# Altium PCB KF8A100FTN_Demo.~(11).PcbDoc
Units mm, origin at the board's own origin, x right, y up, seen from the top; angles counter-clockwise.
Board outline 152.4 x 101.6 mm, 2 copper layers (Top Layer, Bottom Layer); 25 components, 0 nets, 113 pads, 0 vias.
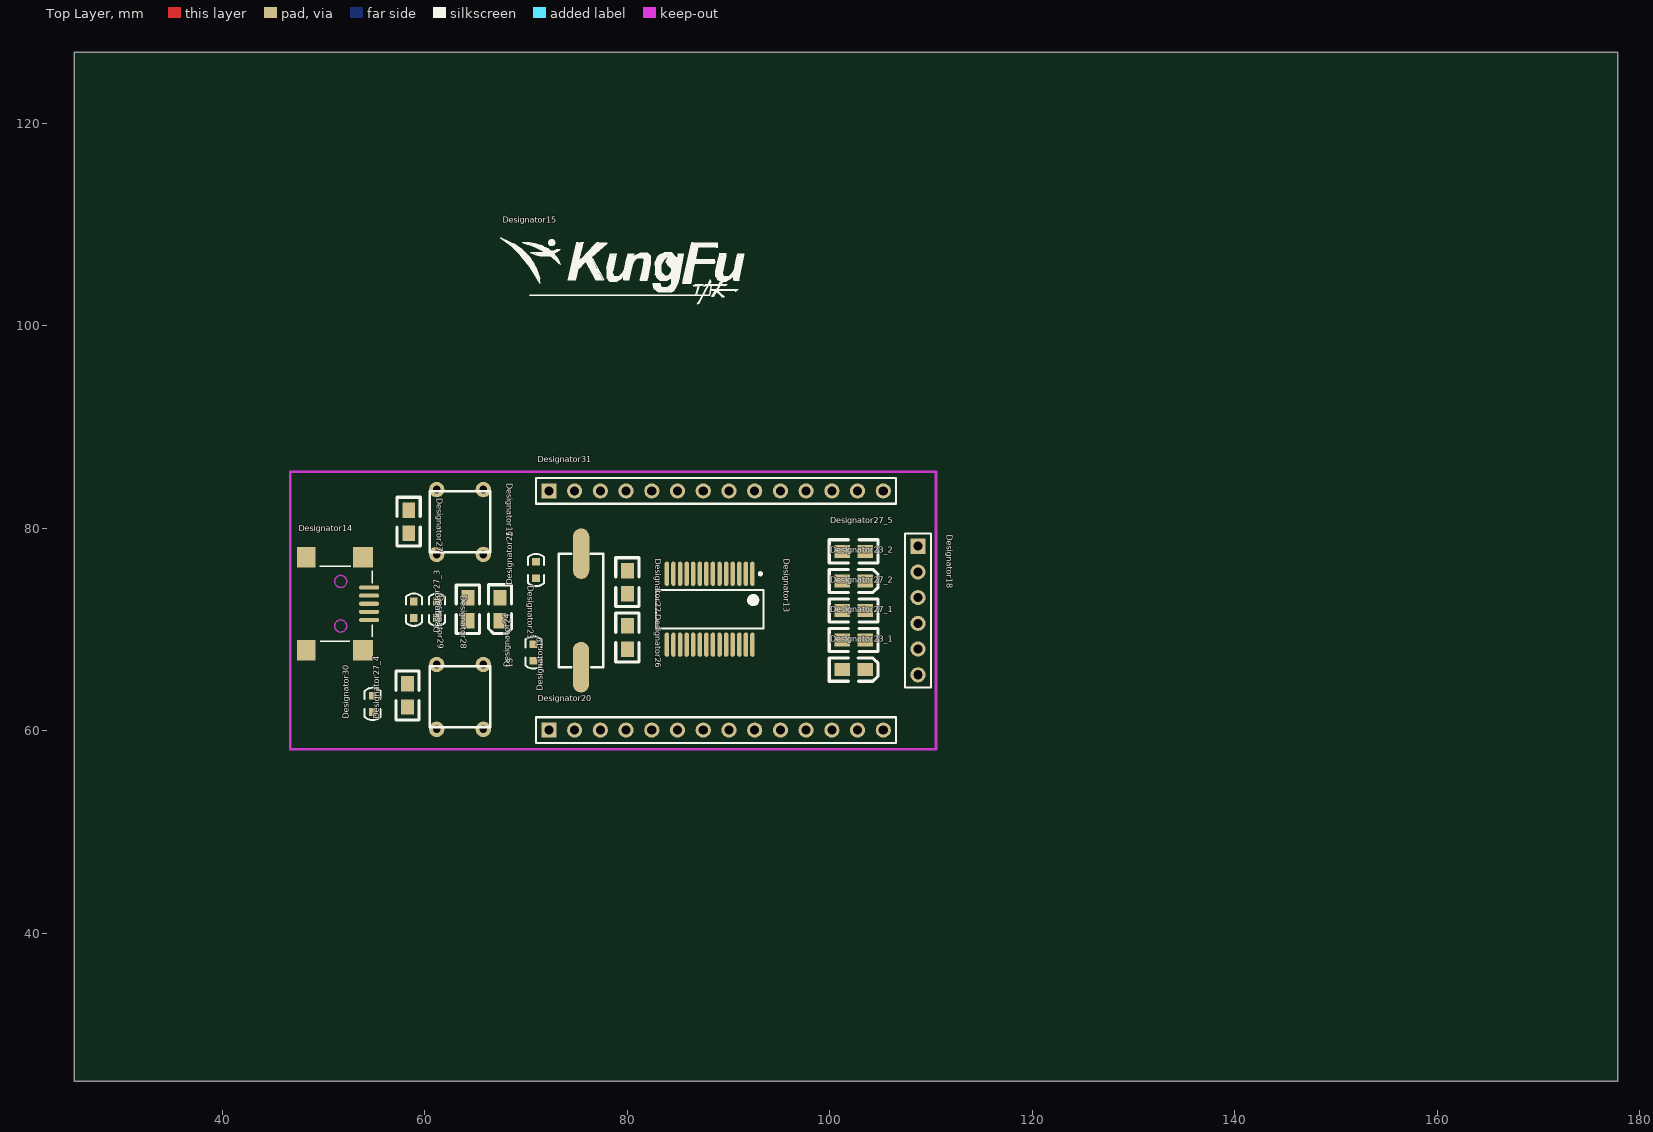
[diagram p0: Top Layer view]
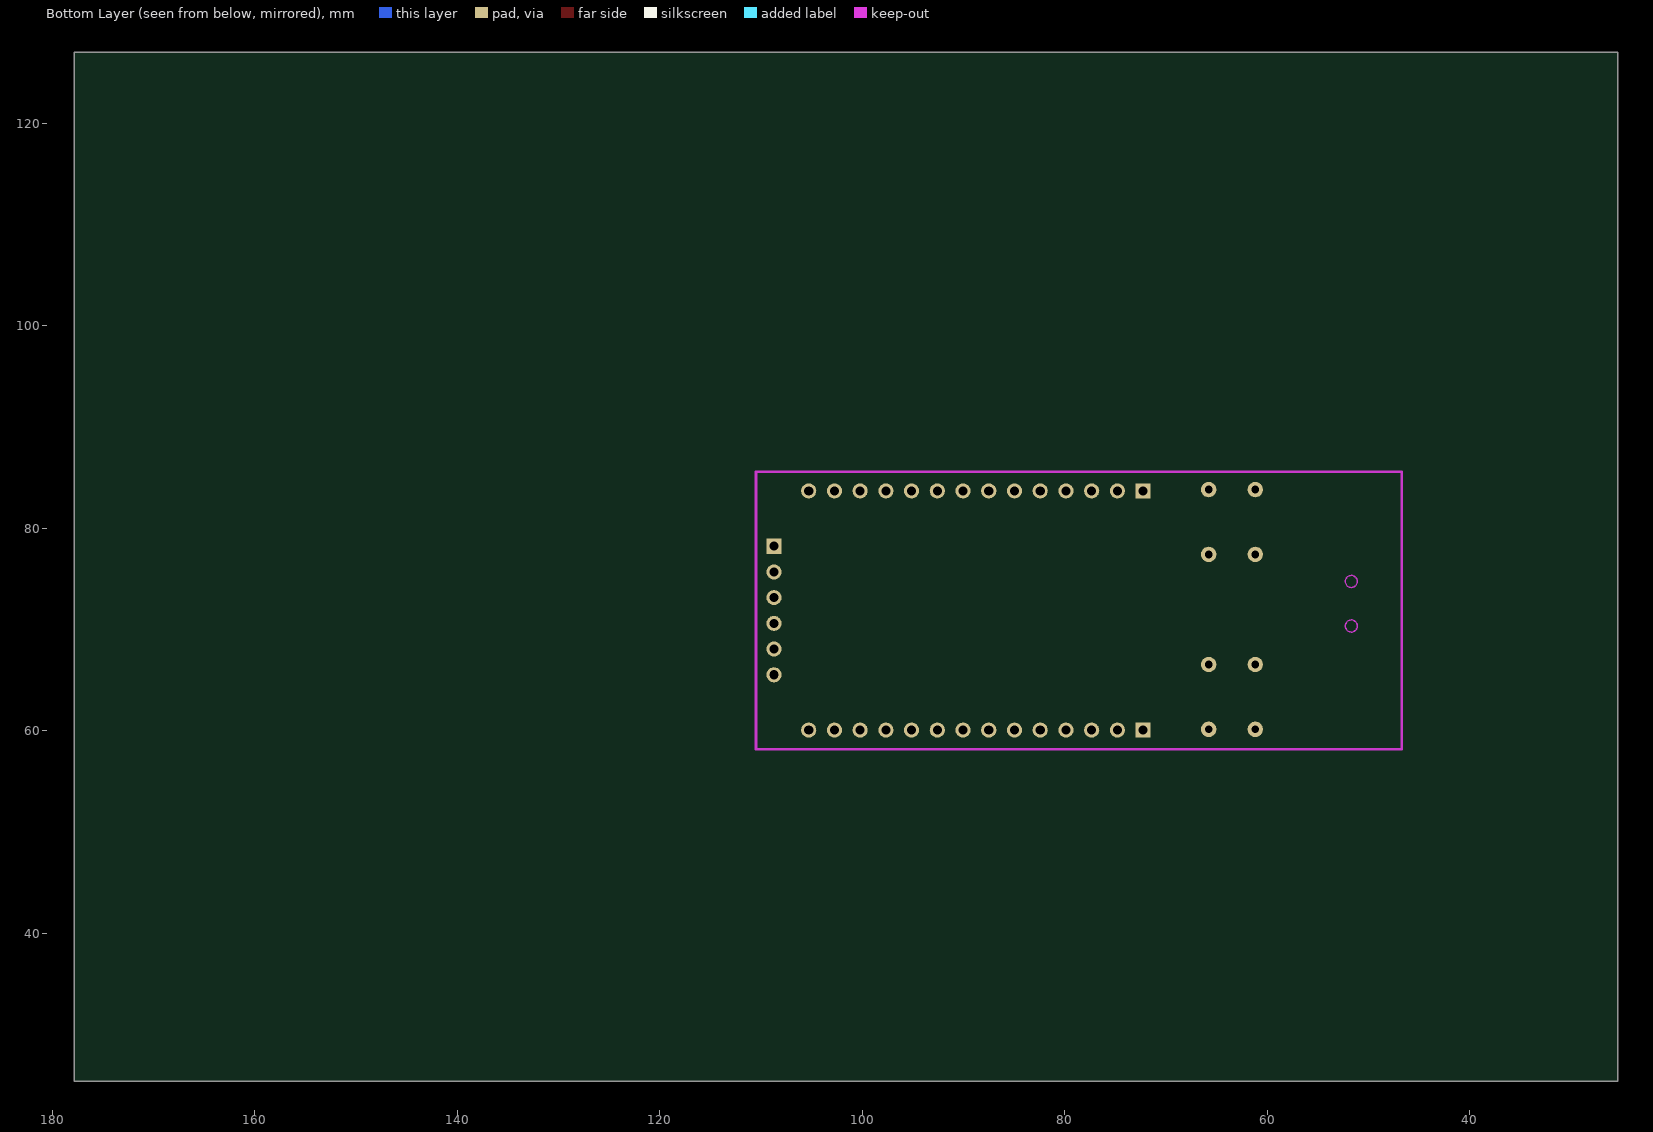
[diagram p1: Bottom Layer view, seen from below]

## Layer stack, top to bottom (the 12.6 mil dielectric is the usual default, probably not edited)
Top Solder: solder mask 0.0102, Solder Resist, Dk 3.5
Top Layer: signal copper 0.0356
Dielectric 1: dielectric 0.32, FR-4, Dk 4.8
Bottom Layer: signal copper 0.0356
Bottom Solder: solder mask 0.0102, Solder Resist, Dk 3.5

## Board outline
25.4,25.4 177.8,25.4 177.8,127 25.4,127

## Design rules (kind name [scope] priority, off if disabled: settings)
Clearance [All] p1: gap=0.254
PolygonConnect [All] p1: connectstyle=Relief reliefconductorwidth=0.254 reliefentries=4 polygonreliefangle="90 Angle" airgapwidth=0.254
RoutingVias [All] p1: holewidth=0.711 width=1.27 viastyle="Through Hole" minholewidth=0.711 minwidth=1.27 maxholewidth=0.711 maxwidth=1.27
SolderMaskExpansion [All] p1: expansion=0.102
UnpouredPolygon [All] p1: allowunpoured=FALSE
Width [All] p1: maxlimit=0.254 minlimit=0.254 preferedwidth=0.254
29 further rules are at their usual default settings.

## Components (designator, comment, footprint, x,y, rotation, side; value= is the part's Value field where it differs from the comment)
Designator13 "Comment" SSOP-SS28_M 88.138,72.009 r270 top
Designator14 "Comment" USB_MINI_B 51.562,73.406 r0 top
Designator15 "Comment" LOGO 70.358,102.997 r0 top
Designator17 "Comment" KEY6*6 65.786,83.82 r270 top
Designator18 "Comment" HDR1X6 108.712,78.232 r270 top
Designator19 "Comment" CRYSTAL 75.438,66.294 r90 top
Designator20 "Comment" HDR1X14 72.263,60.071 r0 top
Designator22 "Comment" 0805 80.01,75.819 r270 top
Designator23 "Comment" D0805 67.437,73.152 r270 top
Designator23_1 "Comment" D0805 101.216,66.04 r0 top
Designator23_2 "Comment" D0805 101.216,74.803 r0 top
Designator24 "Comment" 0603C 70.739,66.929 r90 top
Designator25 "Comment" 0603C 70.993,75.057 r90 top
Designator26 "Comment" 0805 80.01,70.358 r270 top
Designator27 "Comment" 0805 58.42,81.788 r270 top
Designator27_1 "Comment" 0805 101.219,68.961 r0 top
Designator27_2 "Comment" 0805 101.219,71.882 r0 top
Designator27_3 "Comment" 0805 64.262,70.866 r90 top
Designator27_4 "Comment" 0805 58.293,62.357 r90 top
Designator27_5 "Comment" 0805 101.219,77.724 r0 top
Designator28 "Comment" 0603C 61.214,72.771 r270 top
Designator29 "Comment" 0603C 58.928,72.771 r270 top
Designator30 "Comment" 0603C 54.864,61.849 r90 top
Designator31 "Comment" HDR1X14 72.263,83.693 r0 top
S1 "Comment" KEY6*6 65.786,66.548 r270 top

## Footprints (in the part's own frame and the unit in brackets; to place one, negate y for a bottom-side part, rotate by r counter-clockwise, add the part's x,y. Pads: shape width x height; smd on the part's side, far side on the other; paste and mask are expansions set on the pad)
0603C [mil]
  rect 30x30 smd: 1(0,0) 2(64,0)
  silkscreen extent -31,-31 95,31
0805 [mil]
  rect 60x50 smd: 1(-0.11,0) 2(89.89,0)
  silkscreen extent -50,-45 140,45
CRYSTAL [mm]
  oval 5x1.6 smd: 1(0,0) 2(11.2,-0.01)
  silkscreen extent 0,-2.2 11.2,2.2
D0805 [mil]
  rect 60x50 smd: 1(0,0) 2(90,0)
  silkscreen extent -50,-45 140,45
HDR1X6 [mm] "Connector; Header; 6 Position"
  rect 1.5x1.5 hole 0.9: 1(0,0)
  round 1.5 hole 0.9: 2(2.54,0) 3(5.08,0) 4(7.62,0) 5(10.16,0) 6(12.7,0)
  silkscreen extent -1.27,-1.27 13.97,1.27
HDR1X14 [mm] "Connector; Header; 14 Position"
  rect 1.5x1.5 hole 0.9: 1(0,0)
  round 1.5 hole 0.9: 2(2.54,0) 3(5.08,0) 4(7.62,0) 5(10.16,0) 6(12.7,0) 7(15.24,0) 8(17.78,0) 9(20.32,0) 10(22.86,0) 11(25.4,0) 12(27.94,0) 13(30.48,0) 14(33.02,0)
  silkscreen extent -1.27,-1.27 34.29,1.27
KEY6*6 [mil]
  round 60 hole 30: 1(0,0) 2(0,-181.1) 3(251.97,0) 4(251.97,-181.1)
  silkscreen extent 7,-209 243,28
LOGO [mm]
  silkscreen extent -2.9,-0.84 21.21,5.71
SSOP-SS28_M [mm] "SOP, 28-Leads, Body 10.2x5.2mm, Pitch 0.65mm, IPC Low Density"
  oval 2.4x0.45 smd: 1(-3.5,4.225) 2(-3.5,3.575) 3(-3.5,2.925) 4(-3.5,2.275) 5(-3.5,1.625) 6(-3.5,0.975) 7(-3.5,0.325) 8(-3.5,-0.325) 9(-3.5,-0.975) 10(-3.5,-1.625) 11(-3.5,-2.275) 12(-3.5,-2.925) 13(-3.5,-3.575) 14(-3.5,-4.225) 15(3.5,-4.225) 16(3.5,-3.575) 17(3.5,-2.925) 18(3.5,-2.275) 19(3.5,-1.625) 20(3.5,-0.975) 21(3.5,-0.325) 22(3.5,0.325) 23(3.5,0.975) 24(3.5,1.625) 25(3.5,2.275) 26(3.5,2.925) 27(3.5,3.575) 28(3.5,4.225)
  silkscreen extent -3.62,-5.3 1.9,5.3, body extent -2.7,-5.3 2.7,5.3, height 2
USB_MINI_B [mm] "USB_MINI_B"
  oval 2x0.4 smd: 1(2.941,0.744) 2(2.941,-0.056) 3(2.941,-0.856) 4(2.941,-1.656) 5(2.941,-2.456)
  rect 1.797x2 smd: 6(-3.259,-5.456) 6(-3.259,3.744)
  rect 2x2 smd: 6(2.341,-5.456) 6(2.341,3.744)
  Keep-Out Layer circle w0.127: c0.141,1.344 r0.6
  Keep-Out Layer circle w0.127: c0.141,-3.056 r0.6
  silkscreen extent -1.93,-4.58 3.24,2.85

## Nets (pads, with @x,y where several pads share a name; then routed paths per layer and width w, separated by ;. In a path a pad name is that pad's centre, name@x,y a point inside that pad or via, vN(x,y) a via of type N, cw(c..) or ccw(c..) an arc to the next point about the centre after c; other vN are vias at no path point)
pads on no net: Designator13.1 Designator13.2 Designator13.3 Designator13.4 Designator13.5 Designator13.6 Designator13.7 Designator13.8 Designator13.9 Designator13.10 Designator13.11 Designator13.12 Designator13.13 Designator13.14 Designator13.15 Designator13.16 Designator13.17 Designator13.18 Designator13.19 Designator13.20 Designator13.21 Designator13.22 Designator13.23 Designator13.24 Designator13.25 Designator13.26 Designator13.27 Designator13.28 Designator14.1 Designator14.2 Designator14.3 Designator14.4 Designator14.5 Designator14.6 Designator17.1 Designator17.2 Designator17.3 Designator17.4 Designator18.1 Designator18.2 Designator18.3 Designator18.4 Designator18.5 Designator18.6 Designator19.1 Designator19.2 Designator20.1 Designator20.2 Designator20.3 Designator20.4 Designator20.5 Designator20.6 Designator20.7 Designator20.8 Designator20.9 Designator20.10 Designator20.11 Designator20.12 Designator20.13 Designator20.14 Designator22.1 Designator22.2 Designator23.1 Designator23.2 Designator23_1.1 Designator23_1.2 Designator23_2.1 Designator23_2.2 Designator24.1 Designator24.2 Designator25.1 Designator25.2 Designator26.1 Designator26.2 Designator27.1 Designator27.2 Designator27_1.1 Designator27_1.2 Designator27_2.1 Designator27_2.2 Designator27_3.1 Designator27_3.2 Designator27_4.1 Designator27_4.2 Designator27_5.1 Designator27_5.2 Designator28.1 Designator28.2 Designator29.1 Designator29.2 Designator30.1 Designator30.2 Designator31.1 Designator31.2 Designator31.3 Designator31.4 Designator31.5 Designator31.6 Designator31.7 Designator31.8 Designator31.9 Designator31.10 Designator31.11 Designator31.12 Designator31.13 Designator31.14 S1.1 S1.2 S1.3 S1.4

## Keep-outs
Keep-Out Layer:
  lines w0.254: 46.736,58.166 110.49,58.166 110.49,85.598 46.736,85.598 46.736,58.166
